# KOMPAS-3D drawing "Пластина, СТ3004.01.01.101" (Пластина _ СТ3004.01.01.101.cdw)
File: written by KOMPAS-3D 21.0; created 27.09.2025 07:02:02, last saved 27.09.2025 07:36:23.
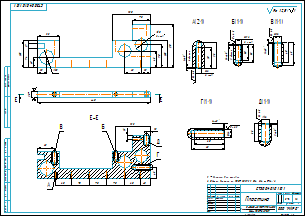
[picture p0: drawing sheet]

Sheet 1: A2, landscape

Document properties: Полное имя файла: C:\Users\Lutik\Yandex.Disk\Документы\Новая папка\Стапель №2\Стапель _ СТ3004.00.00.000\Опора _ СТ3004.01.00.000\2D\Кронштейн _ СТ3004.01.01.000\Основание _ СТ3004.01.01.100\Пластина _ СТ3004.01.01.101.cdw; Знак неуказанной шероховатости: 4; Параметр неуказанной шероховатости: Ra 12,5; Масса: 5.762144

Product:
- Part/product: Пластина  | designation СТ3004.01.01.101
    Материал: Лист$dБ-ПН-НО-25 ГОСТ 19903-2015;Ст3сп ГОСТ 14637-89$ (density 7850 kg/m3)
    Масса: 5.762144

Title block, sheet 1: Наименование: Пластина; designation: СТ3004.01.01.101; Материал: Лист Б-ПН-НО-25 ГОСТ 19903-2015 Ст3сп ГОСТ 14637-89; Масса: 5,76; Количество листов документа: 1; organisation: ООО "МИРО"; Форматы листов документа: A2; Разработал: Тимонин

Views: Вид 1, Снизу, Проекционный вид 3, Разрез А-А, Выносной элемент 5, Выносной элемент 6, Выносной элемент 7, Выносной элемент 8, Выносной элемент 9, Разрез Е-Е, Выносной элемент А, Выносной элемент, Выносной элемент Б, Выносной элемент В, Выносной элемент Г, Выносной элемент Д
Referenced files in C:\Users\Lutik\Yandex.Disk\Документы\Новая папка\Стапель №2\Стапель _ СТ3004.00.00.000\Опора _ СТ3004.01.00.000\3D\Кронштейн _ СТ3004.01.01.000\Основание _ СТ3004.01.01.100\: Пластина _ СТ3004.01.01.101.m3d
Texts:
  Ra 6,3
  Ra 12,5
  Ra 12,5 ( )
  СТ3004.01.01.100
  СТ3004.01.01.101 Пластина
Dimensions and other numbers on the sheet: 35; 65; 90; 55; 40; 76; 17; 50; 2 отв.; 105; 170; 70; 150; 85; 440; 25; 45; 15; 135; 60; 6; 6 отв.; 20; 1; 6 фасок; 30; 1,6; 2 фаски; 12; 16; 2; 1:2; 5,76

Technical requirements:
  * Размеры для справок.
  Общие допуски по ГОСТ 30893.1: Н14, h14, ± IT14/2.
